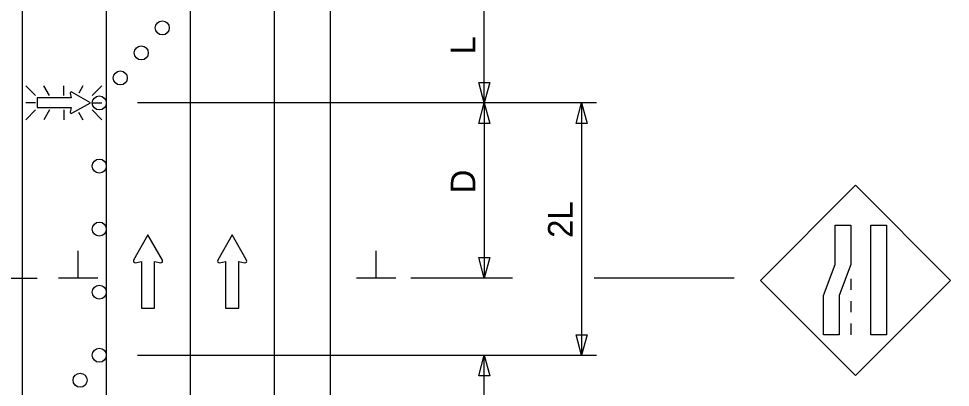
# Model space of a CAD drawing. Extents: x 16553 to 18478, y 5759 to 7026.
# Drawn here: x 16886.6 to 17152.9, y 6582.5 to 6687.7 of the extents above; entities that cross this region are included whole.
import ezdxf

# ---------------------------------------------------------------- set-up
doc = ezdxf.new("R2010")
doc.units = 0
for name, color, linetype in [('ALI_LEGAL_EX', 7, 'Continuous'), ('MT_SCRATCH_LEVEL_E', 7, 'Continuous'), ('PAVT_EDGE_EX', 7, 'Continuous'), ('TRAFFIC_SIGNS_PR', 7, 'Continuous'), ('TYPICAL_TEXT_DIMEN_PR', 7, 'Continuous')]:
    doc.layers.add(name, color=color, linetype=linetype)

msp = doc.modelspace()

# ---------------------------------------------------------------- linework, layer by layer
at = {"layer": 'ALI_LEGAL_EX'}
for p, q in [((16911.66, 7026.35), (16911.66, 6197.16)), ((16935.66, 7026.35), (16935.66, 6197.16)), ((16935.66, 7026.35), (16935.66, 6197.16))]:
    msp.add_line(p, q, dxfattribs=at)
for points in [[(16911.66, 6626.35), (16911.66, 6601.35)], [(16935.66, 6626.35), (16935.66, 6601.35)]]:
    msp.add_lwpolyline(points, dxfattribs=at)
at = {"layer": 'MT_SCRATCH_LEVEL_E'}
for p, q in [((16923.57, 6625.97), (16919.46, 6618.73)), ((16927.71, 6618.73), (16923.57, 6625.97)), ((16947.62, 6625.97), (16943.51, 6618.73)), ((16951.77, 6618.73), (16947.62, 6625.97)), ((16919.94, 6618.04), (16921.72, 6618.36)), ((16921.72, 6618.36), (16921.72, 6605.1)), ((16925.46, 6605.1), (16925.46, 6618.36)), ((16925.46, 6618.36), (16927.23, 6618.04)), ((16943.99, 6618.04), (16945.77, 6618.36)), ((16945.77, 6618.36), (16945.77, 6605.1)), ((16949.51, 6605.1), (16949.51, 6618.36)), ((16949.51, 6618.36), (16951.29, 6618.04)), ((16921.72, 6605.1), (16925.46, 6605.1)), ((16945.77, 6605.1), (16949.51, 6605.1))]:
    msp.add_line(p, q, dxfattribs=at)
for centre, start, end in [((16919.86, 6618.5), 150.4248, 279.9638), ((16927.3, 6618.5), 260.0362, 29.7731), ((16943.92, 6618.5), 150.4248, 279.9638), ((16951.36, 6618.5), 260.0362, 29.7731)]:
    msp.add_arc(centre, 0.463, start, end, dxfattribs=at)
at = {"layer": 'PAVT_EDGE_EX'}
for p, q in [((16887.66, 6926.66), (16887.66, 6223.96)), ((16959.66, 6926.66), (16959.66, 6223.96)), ((16975.66, 6926.66), (16975.66, 6223.96))]:
    msp.add_line(p, q, dxfattribs=at)
at = {"layer": 'TRAFFIC_SIGNS_PR'}
for p, q in [((16891.44, 6665.74), (16888.62, 6668.56)), ((16893.74, 6668.56), (16895.36, 6665.74)), ((16899.52, 6665.74), (16899.52, 6668.56)), ((16904.99, 6668.56), (16903.79, 6666.46)), ((16910.43, 6668.55), (16907.61, 6665.74)), ((16891.44, 6663.7), (16888.62, 6663.7)), ((16907.61, 6663.7), (16910.43, 6663.7)), ((16891.44, 6661.67), (16888.62, 6658.85)), ((16895.39, 6661.67), (16893.76, 6658.85)), ((16899.52, 6661.67), (16899.52, 6658.85)), ((16903.71, 6661.04), (16904.97, 6658.85)), ((16910.43, 6658.85), (16907.61, 6661.67)), ((17125.73, 6640.14), (17098.58, 6612.99)), ((17152.88, 6612.99), (17125.73, 6640.14)), ((17098.58, 6612.99), (17125.73, 6585.84)), ((17124.48, 6613.48), (17124.48, 6610.28)), ((17125.73, 6585.84), (17152.88, 6612.99)), ((17124.48, 6607.08), (17124.48, 6603.88)), ((17124.48, 6600.68), (17124.48, 6597.48))]:
    msp.add_line(p, q, dxfattribs=at)
for points in [[(16901.35, 6666.39), (16901.58, 6665.09), (16891.86, 6665.09), (16891.86, 6662.35), (16901.58, 6662.35), (16901.35, 6661.04)], [(16901.85, 6660.69), (16907.16, 6663.7), (16901.85, 6666.74)]]:
    msp.add_lwpolyline(points, dxfattribs=at)
for points in [[(17124.48, 6628.73), (17124.48, 6617.55), (17121.14, 6608.66), (17121.14, 6597.48), (17116.64, 6597.48), (17116.64, 6608.66), (17119.99, 6617.55), (17119.99, 6628.73)], [(17134.62, 6628.73), (17134.62, 6597.48), (17130.12, 6597.48), (17130.12, 6628.73)]]:
    msp.add_lwpolyline(points, close=True, dxfattribs=at)
for centre in [(16927.66, 6685.05), (16921.66, 6677.91), (16915.66, 6670.77), (16909.66, 6663.63), (16909.66, 6645.63), (16909.66, 6627.63), (16909.66, 6609.63), (16909.66, 6591.63), (16904.17, 6584.5)]:
    msp.add_circle(centre, 2, dxfattribs=at)
for centre, start, end in [((16901.69, 6666.44), 61.4833, 189.9593), ((16901.69, 6660.99), 170.7308, 298.8916)]:
    msp.add_arc(centre, 0.341, start, end, dxfattribs=at)
at = {"layer": 'TYPICAL_TEXT_DIMEN_PR'}
for p, q in [((17019.66, 6663.63), (17019.66, 6694.2)), ((17019.66, 6663.63), (17018.09, 6669.49)), ((17018.09, 6669.49), (17019.66, 6669.49)), ((17019.66, 6669.49), (17021.23, 6669.49)), ((17021.23, 6669.49), (17019.66, 6663.63)), ((17051.71, 6663.63), (16920.56, 6663.63)), ((17018.09, 6657.77), (17019.66, 6663.63)), ((17019.66, 6663.63), (17019.66, 6613.63)), ((17019.66, 6663.63), (17021.23, 6657.77)), ((17045.9, 6657.77), (17047.47, 6663.63)), ((17047.47, 6663.63), (17049.04, 6657.77)), ((17047.47, 6663.63), (17047.47, 6591.63)), ((17019.66, 6657.77), (17018.09, 6657.77)), ((17021.23, 6657.77), (17019.66, 6657.77)), ((17047.47, 6657.77), (17045.9, 6657.77)), ((17049.04, 6657.77), (17047.47, 6657.77)), ((16903.59, 6613.63), (16903.59, 6621.42)), ((16988.79, 6613.63), (16988.79, 6621.42)), ((17019.66, 6613.63), (17018.09, 6619.49)), ((17018.09, 6619.49), (17019.66, 6619.49)), ((17019.66, 6619.49), (17021.23, 6619.49)), ((17021.23, 6619.49), (17019.66, 6613.63)), ((17047.47, 6618.5), (17047.47, 6614.73)), ((16812.66, 6613.63), (16891.86, 6613.63)), ((16909.22, 6613.63), (16897.97, 6613.63)), ((16994.41, 6613.63), (16983.16, 6613.63)), ((17027.77, 6613.63), (16998.66, 6613.63)), ((17091.09, 6613.63), (17051.1, 6613.63)), ((17047.47, 6591.63), (17045.9, 6597.49)), ((17045.9, 6597.49), (17047.47, 6597.49)), ((17047.47, 6597.49), (17049.04, 6597.49)), ((17049.04, 6597.49), (17047.47, 6591.63)), ((16920.56, 6591.63), (17051.71, 6591.63)), ((17018.09, 6585.77), (17019.66, 6591.63)), ((17019.66, 6561.07), (17019.66, 6591.63)), ((17019.66, 6591.63), (17021.23, 6585.77)), ((17019.66, 6585.77), (17018.09, 6585.77)), ((17021.23, 6585.77), (17019.66, 6585.77))]:
    msp.add_line(p, q, dxfattribs=at)

# ---------------------------------------------------------------- texts
for s, p in [('L', (17017.1, 6677.49)), ('D', (17017.1, 6637.85)), ('2L', (17044.91, 6625.14))]:
    msp.add_text(s, height=7, rotation=90, dxfattribs=at).set_placement(p)

doc.saveas('drawing.dxf')
